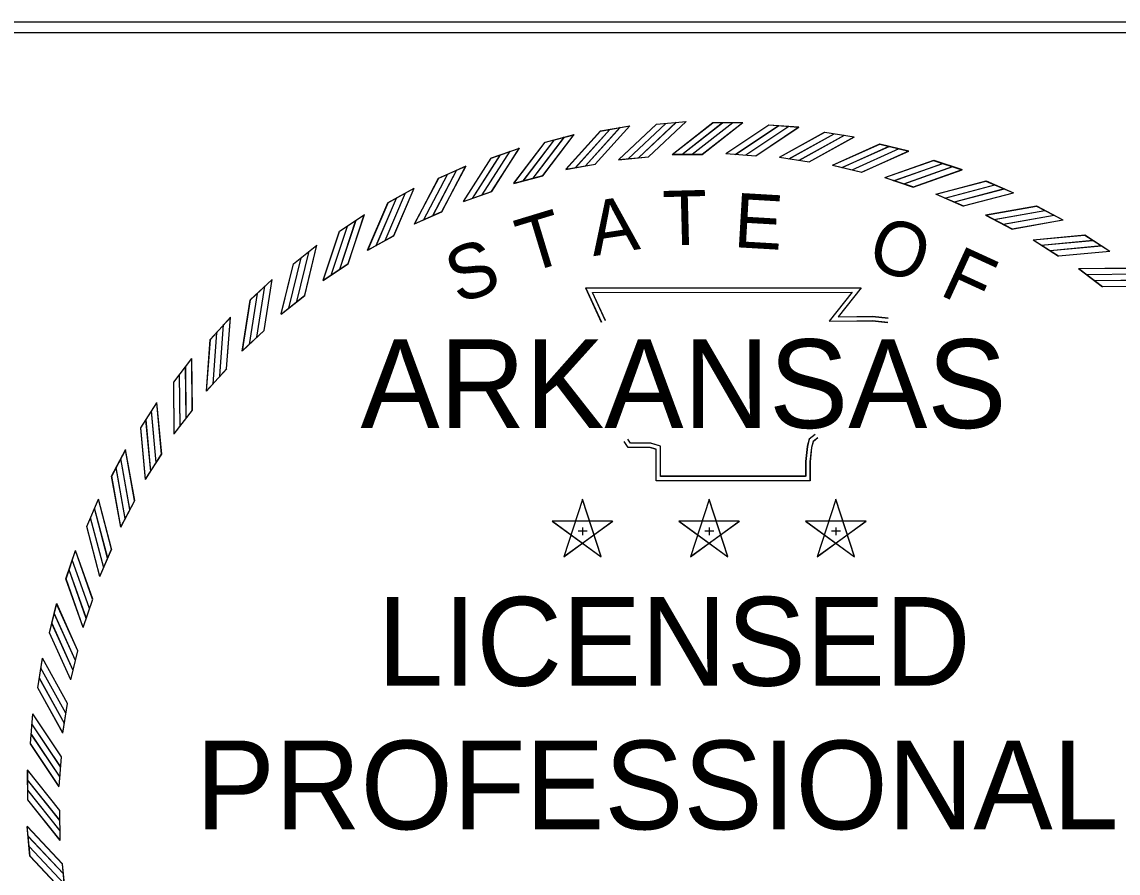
# Model space of a CAD drawing. Extents: x 0 to 1228740, y 0 to 152440.
# Drawn here: x 30.834 to 32.765, y 18.662 to 20.162 of the extents above; entities that cross this region are included whole.
import ezdxf

# ---------------------------------------------------------------- set-up
doc = ezdxf.new("R2010")
doc.units = 0
for name, color, linetype in [('R_Border', 7, 'Continuous'), ('R_No Plot', 7, 'Continuous'), ('R_Sheet Text', 7, 'Continuous'), ('STAMP', 7, 'Continuous')]:
    doc.layers.add(name, color=color, linetype=linetype)

msp = doc.modelspace()

# ---------------------------------------------------------------- linework, layer by layer
at = {"layer": 'R_Border'}
msp.add_line((29.1131, 20.1432), (33.4231, 20.1432), dxfattribs=at)
at = {"layer": 'R_No Plot'}
msp.add_lwpolyline([(30.6665, 20.1618), (33.4231, 20.1618), (33.4231, 17.4052), (30.6665, 17.4052)], close=True, dxfattribs=at)
at = {"layer": 'R_Sheet Text'}
for p, q in [((31.8532, 19.9696), (31.905, 19.9787)), ((31.9517, 19.9814), (32.0041, 19.9862)), ((32.0514, 19.9843), (32.104, 19.9843)), ((32.1499, 19.9804), (32.2025, 19.9765)), ((32.1499, 19.9803), (32.2024, 19.9765)), ((32.2483, 19.9676), (32.3003, 19.9594)), ((31.756, 19.9497), (31.8069, 19.9631)), ((31.6608, 19.9219), (31.7104, 19.9395)), ((32.0741, 19.9298), (32.1268, 19.9259)), ((32.0742, 19.9298), (32.1268, 19.9259)), ((32.3453, 19.9467), (32.3964, 19.9343)), ((31.7922, 19.902), (31.8442, 19.9111)), ((31.8853, 19.919), (31.9379, 19.9238)), ((31.9795, 19.9283), (32.0323, 19.9283)), ((32.1686, 19.9234), (32.2207, 19.9152)), ((32.4402, 19.9179), (32.4901, 19.9013)), ((31.5682, 19.8863), (31.6162, 19.9079)), ((31.7008, 19.8773), (31.7518, 19.8907)), ((32.2623, 19.9093), (32.3135, 19.8968)), ((32.3544, 19.8875), (32.4044, 19.8708)), ((32.5324, 19.8814), (32.5808, 19.8607)), ((31.4789, 19.8432), (31.5249, 19.8687)), ((31.6118, 19.8452), (31.6615, 19.8628)), ((32.4444, 19.8582), (32.4929, 19.8374)), ((32.6213, 19.8374), (32.6678, 19.8128)), ((31.3934, 19.7929), (31.4372, 19.8221)), ((31.5257, 19.8058), (31.5738, 19.8274)), ((32.5316, 19.8215), (32.5783, 19.7968)), ((31.4431, 19.7595), (31.4893, 19.785)), ((32.6156, 19.7777), (32.66, 19.7493)), ((32.7063, 19.7862), (32.7506, 19.7578)), ((31.3124, 19.7356), (31.3536, 19.7683)), ((31.3647, 19.7064), (31.4086, 19.7357)), ((32.6956, 19.7272), (32.7376, 19.6952)), ((31.2364, 19.6719), (31.2748, 19.7079)), ((31.2909, 19.6471), (31.3323, 19.6799)), ((31.1659, 19.6021), (31.2012, 19.6412)), ((31.2223, 19.582), (31.2608, 19.618)), ((31.1014, 19.5268), (31.1333, 19.5686)), ((31.1593, 19.5113), (31.1946, 19.5504)), ((31.0433, 19.4463), (31.0717, 19.4907)), ((31.1023, 19.4357), (31.1343, 19.4776)), ((30.9921, 19.3614), (31.0167, 19.4079)), ((31.0518, 19.3557), (31.0802, 19.4001)), ((30.9481, 19.2725), (30.9688, 19.3209)), ((31.008, 19.2717), (31.0327, 19.3183)), ((31.8214, 19.3203), (31.7885, 19.2193)), ((31.8542, 19.2194), (31.8215, 19.3205)), ((32.0446, 19.3203), (32.0117, 19.2193)), ((32.0774, 19.2194), (32.0447, 19.3205)), ((32.2678, 19.3203), (32.2349, 19.2193)), ((32.3006, 19.2194), (32.2679, 19.3205)), ((31.8745, 19.2818), (31.7682, 19.2819)), ((31.7683, 19.2818), (31.8542, 19.2193)), ((31.7886, 19.2194), (31.8746, 19.2818)), ((32.0977, 19.2818), (31.9914, 19.2819)), ((31.9915, 19.2818), (32.0774, 19.2193)), ((32.0118, 19.2194), (32.0978, 19.2818)), ((32.3209, 19.2818), (32.2147, 19.2819)), ((32.2147, 19.2818), (32.3006, 19.2193)), ((32.235, 19.2194), (32.321, 19.2818)), ((31.8138, 19.2648), (31.8296, 19.2648)), ((31.8215, 19.2705), (31.8215, 19.2572)), ((32.037, 19.2648), (32.0528, 19.2648)), ((32.0447, 19.2705), (32.0447, 19.2572)), ((32.2603, 19.2648), (32.276, 19.2648)), ((32.2679, 19.2705), (32.2679, 19.2572)), ((30.9116, 19.1803), (30.9282, 19.2302)), ((30.9713, 19.1844), (30.9921, 19.2329)), ((30.942, 19.0944), (30.9587, 19.1445)), ((30.8828, 19.0853), (30.8952, 19.1365)), ((30.9202, 19.0023), (30.9327, 19.0536)), ((30.8619, 18.9884), (30.8701, 19.0403)), ((30.9061, 18.9087), (30.9143, 18.9608)), ((30.8492, 18.89), (30.853, 18.9425)), ((30.8997, 18.8143), (30.9036, 18.8669)), ((30.8446, 18.7909), (30.8441, 18.8435)), ((30.9012, 18.7196), (30.9007, 18.7724)), ((30.8481, 18.6918), (30.8433, 18.7442)), ((30.9105, 18.6254), (30.9057, 18.6779))]:
    msp.add_line(p, q, dxfattribs=at)
for points in [[(31.7922, 19.9019), (31.8531, 19.9695)], [(31.8089, 19.9047), (31.8699, 19.9723)], [(31.8268, 19.9083), (31.8878, 19.9759)], [(31.8441, 19.9112), (31.9051, 19.9788)], [(31.8853, 19.919), (31.9516, 19.9813)], [(31.9022, 19.9203), (31.9685, 19.9827)], [(31.9203, 19.9224), (31.9867, 19.9848)], [(31.9378, 19.9239), (32.0042, 19.9862)], [(31.9795, 19.9282), (32.0513, 19.9842)], [(31.9964, 19.9281), (32.0682, 19.9841)], [(32.0147, 19.9285), (32.0865, 19.9845)], [(32.0322, 19.9283), (32.104, 19.9843)], [(32.0741, 19.9297), (32.1499, 19.9804)], [(32.0741, 19.9297), (32.1498, 19.9803)], [(32.091, 19.9283), (32.1668, 19.979)], [(32.091, 19.9283), (32.1667, 19.9789)], [(32.1092, 19.9274), (32.1851, 19.978)], [(32.1093, 19.9274), (32.185, 19.978)], [(32.1267, 19.9259), (32.2025, 19.9766)], [(32.1267, 19.9259), (32.2025, 19.9765)], [(32.1686, 19.9234), (32.2482, 19.9675)], [(31.7008, 19.8772), (31.756, 19.9497)], [(31.7172, 19.8814), (31.7724, 19.9538)], [(31.7348, 19.8864), (31.79, 19.9589)], [(31.7518, 19.8907), (31.807, 19.9632)], [(32.1853, 19.9206), (32.2649, 19.9647)], [(32.2034, 19.9182), (32.283, 19.9623)], [(32.2207, 19.9153), (32.3003, 19.9594)], [(31.6449, 19.8571), (31.6939, 19.9338)], [(31.6614, 19.8628), (31.7105, 19.9395)], [(32.2622, 19.9093), (32.3452, 19.9467)], [(32.2786, 19.9051), (32.3616, 19.9425)], [(32.2965, 19.9012), (32.3795, 19.9386)], [(32.3134, 19.8969), (32.3965, 19.9343)], [(31.6117, 19.8451), (31.6608, 19.9218)], [(31.6278, 19.8506), (31.6768, 19.9273)], [(32.3543, 19.8875), (32.4401, 19.9179)], [(32.3703, 19.882), (32.4561, 19.9124)], [(31.5412, 19.8125), (31.5837, 19.893)], [(31.5577, 19.8204), (31.6002, 19.9009)], [(31.5737, 19.8274), (31.6162, 19.908)], [(32.3878, 19.8766), (32.4736, 19.907)], [(32.4044, 19.8709), (32.4902, 19.9013)], [(31.5257, 19.8057), (31.5682, 19.8862)], [(32.4443, 19.8581), (32.5323, 19.8814)], [(32.4598, 19.8513), (32.5478, 19.8746)], [(31.4738, 19.7766), (31.5095, 19.8604)], [(31.4892, 19.785), (31.525, 19.8687)], [(32.4768, 19.8445), (32.5648, 19.8678)], [(32.4928, 19.8375), (32.5809, 19.8607)], [(31.4431, 19.7594), (31.4788, 19.8431)], [(31.458, 19.7674), (31.4937, 19.8512)], [(32.5316, 19.8215), (32.6212, 19.8374)], [(31.4085, 19.7357), (31.4372, 19.8221)], [(32.5465, 19.8134), (32.6361, 19.8293)], [(32.5628, 19.8052), (32.6525, 19.8211)], [(31.3789, 19.7156), (31.4076, 19.8021)], [(31.3939, 19.7261), (31.4225, 19.8125)], [(32.5782, 19.7969), (32.6679, 19.8128)], [(31.3647, 19.7064), (31.3934, 19.7928)], [(32.6155, 19.7777), (32.7062, 19.7862)], [(32.6297, 19.7685), (32.7204, 19.7769)], [(31.3183, 19.6691), (31.3398, 19.7576)], [(31.3322, 19.6799), (31.3536, 19.7684)], [(32.6453, 19.7589), (32.736, 19.7674)], [(32.66, 19.7494), (32.7506, 19.7578)], [(31.3043, 19.6575), (31.3257, 19.746)], [(31.2909, 19.6471), (31.3124, 19.7356)], [(32.6956, 19.7272), (32.7866, 19.7281)], [(32.7089, 19.7168), (32.8, 19.7177)], [(31.2607, 19.618), (31.2748, 19.708)], [(32.7237, 19.706), (32.8147, 19.707)], [(31.2347, 19.5933), (31.2488, 19.6833)], [(31.2478, 19.6061), (31.2619, 19.6961)], [(31.8553, 19.6321), (31.8272, 19.6928), (32.3126, 19.6931), (32.272, 19.6422), (32.305, 19.6426), (32.3325, 19.643), (32.36, 19.64)], [(31.8623, 19.6353), (31.8393, 19.6852), (32.2966, 19.6854), (32.2559, 19.6343), (32.3051, 19.6349), (32.3322, 19.6353), (32.3592, 19.6323)], [(32.7375, 19.6953), (32.8286, 19.6962)], [(31.2223, 19.5819), (31.2363, 19.6718)], [(31.1946, 19.5504), (31.2012, 19.6412)], [(31.1827, 19.5375), (31.1893, 19.6283)], [(31.1593, 19.5112), (31.1659, 19.6021)], [(31.1707, 19.5237), (31.1773, 19.6145)], [(31.1342, 19.4776), (31.1333, 19.5687)], [(31.1235, 19.4638), (31.1225, 19.5548)], [(31.1023, 19.4356), (31.1014, 19.5267)], [(31.1127, 19.449), (31.1118, 19.54)], [(31.0801, 19.4001), (31.0717, 19.4907)], [(31.0706, 19.3854), (31.0621, 19.476)], [(31.0518, 19.3556), (31.0433, 19.4462)], [(31.061, 19.3698), (31.0526, 19.4604)], [(32.2361, 19.4287), (32.2278, 19.422), (32.2251, 19.4119), (32.2223, 19.3868), (32.2223, 19.3532), (31.9514, 19.3532), (31.9514, 19.3985), (31.9514, 19.4086), (31.9404, 19.4119), (31.9019, 19.4119), (31.895, 19.4224)], [(32.2312, 19.4347), (32.2211, 19.4264), (32.2175, 19.4134), (32.2146, 19.3872), (32.2146, 19.3609), (31.9591, 19.3609), (31.9591, 19.3985), (31.9591, 19.4142), (31.9416, 19.4196), (31.906, 19.4196), (31.9015, 19.4266)], [(31.0326, 19.3183), (31.0167, 19.408)], [(31.0243, 19.3029), (31.0084, 19.3925)], [(31.0161, 19.2865), (31.0002, 19.3762)], [(31.008, 19.2716), (30.9921, 19.3613)], [(30.992, 19.2329), (30.9688, 19.3209)], [(30.985, 19.2168), (30.9617, 19.3049)], [(30.9714, 19.1844), (30.9481, 19.2724)], [(30.9782, 19.1999), (30.9549, 19.2879)], [(30.9586, 19.1444), (30.9282, 19.2303)], [(30.9475, 19.1104), (30.9171, 19.1962)], [(30.9529, 19.1279), (30.9225, 19.2137)], [(30.942, 19.0944), (30.9116, 19.1802)], [(30.9283, 19.0365), (30.8909, 19.1195)], [(30.9326, 19.0535), (30.8952, 19.1365)], [(30.9244, 19.0187), (30.887, 19.1017)], [(30.9202, 19.0023), (30.8828, 19.0853)], [(30.9113, 18.9435), (30.8672, 19.0231)], [(30.9142, 18.9608), (30.8701, 19.0404)], [(30.9089, 18.9254), (30.8648, 19.005)], [(30.9061, 18.9087), (30.862, 18.9883)], [(30.9021, 18.8493), (30.8515, 18.9251)], [(30.9036, 18.8668), (30.853, 18.9425)], [(30.9012, 18.8311), (30.8506, 18.9068)], [(30.8998, 18.8142), (30.8492, 18.8899)], [(30.9007, 18.7723), (30.844, 18.8436)], [(30.9007, 18.7548), (30.844, 18.826)], [(30.9013, 18.7365), (30.8446, 18.8078)], [(30.9013, 18.7196), (30.8446, 18.7908)], [(30.9056, 18.6779), (30.8433, 18.7442)], [(30.9071, 18.6604), (30.8447, 18.7268)], [(30.9091, 18.6422), (30.8468, 18.7086)], [(30.9105, 18.6254), (30.8482, 18.6917)]]:
    msp.add_lwpolyline(points, dxfattribs=at)
at = {"layer": 'STAMP'}
for p, q in [((31.8534, 19.9698), (31.9052, 19.9789)), ((31.9519, 19.9816), (32.0043, 19.9864)), ((32.0515, 19.9845), (32.1041, 19.9845)), ((32.1501, 19.9806), (32.2027, 19.9767)), ((32.1501, 19.9805), (32.2026, 19.9767)), ((32.2485, 19.9678), (32.3004, 19.9596)), ((31.7562, 19.9499), (31.8071, 19.9633)), ((31.661, 19.9221), (31.7106, 19.9396)), ((32.0743, 19.93), (32.127, 19.9261)), ((32.0744, 19.93), (32.127, 19.9261)), ((32.3454, 19.9469), (32.3966, 19.9345)), ((31.7924, 19.9022), (31.8443, 19.9113)), ((31.8855, 19.9192), (31.938, 19.924)), ((31.9797, 19.9285), (32.0324, 19.9285)), ((32.1688, 19.9236), (32.2209, 19.9154)), ((32.2624, 19.9095), (32.3137, 19.897)), ((32.4404, 19.9181), (32.4903, 19.9015)), ((31.5684, 19.8865), (31.6164, 19.9081)), ((31.701, 19.8775), (31.752, 19.8909)), ((32.3545, 19.8877), (32.4046, 19.871)), ((32.5326, 19.8816), (32.581, 19.8609)), ((31.479, 19.8434), (31.5251, 19.8689)), ((31.6119, 19.8454), (31.6616, 19.863)), ((32.4445, 19.8583), (32.493, 19.8376)), ((32.6215, 19.8376), (32.668, 19.813)), ((31.3935, 19.7931), (31.4373, 19.8222)), ((31.5258, 19.806), (31.5739, 19.8276)), ((32.5318, 19.8217), (32.5784, 19.797)), ((31.4433, 19.7596), (31.4894, 19.7852)), ((32.6158, 19.7779), (32.6602, 19.7495)), ((32.7064, 19.7864), (32.7508, 19.758)), ((31.3125, 19.7358), (31.3537, 19.7685)), ((31.3648, 19.7066), (31.4087, 19.7359)), ((32.6958, 19.7274), (32.7377, 19.6954)), ((31.2365, 19.6721), (31.2749, 19.7081)), ((31.2911, 19.6473), (31.3324, 19.6801)), ((31.166, 19.6023), (31.2013, 19.6414)), ((31.2224, 19.5821), (31.2609, 19.6182)), ((31.1015, 19.527), (31.1334, 19.5688)), ((31.1594, 19.5115), (31.1948, 19.5506)), ((31.0434, 19.4465), (31.0718, 19.4908)), ((31.1024, 19.4359), (31.1344, 19.4778)), ((30.9922, 19.3616), (31.0169, 19.4081)), ((31.0519, 19.3558), (31.0803, 19.4003)), ((30.9482, 19.2727), (30.9689, 19.321)), ((31.0081, 19.2719), (31.0328, 19.3185)), ((31.8215, 19.3205), (31.7886, 19.2195)), ((31.8543, 19.2196), (31.8216, 19.3206)), ((32.0448, 19.3205), (32.0118, 19.2195)), ((32.0776, 19.2196), (32.0448, 19.3206)), ((32.268, 19.3205), (32.2351, 19.2195)), ((32.3008, 19.2196), (32.2681, 19.3206)), ((31.8746, 19.282), (31.7684, 19.2821)), ((31.7685, 19.282), (31.8544, 19.2194)), ((31.7887, 19.2196), (31.8748, 19.2819)), ((32.0978, 19.282), (31.9916, 19.2821)), ((31.9917, 19.282), (32.0776, 19.2194)), ((32.012, 19.2196), (32.098, 19.2819)), ((32.3211, 19.282), (32.2148, 19.2821)), ((32.2149, 19.282), (32.3008, 19.2194)), ((32.2352, 19.2196), (32.3212, 19.2819)), ((31.814, 19.265), (31.8298, 19.265)), ((31.8216, 19.2707), (31.8216, 19.2573)), ((32.0372, 19.265), (32.053, 19.265)), ((32.0449, 19.2707), (32.0449, 19.2573)), ((32.2604, 19.265), (32.2762, 19.265)), ((32.2681, 19.2707), (32.2681, 19.2573)), ((30.9117, 19.1804), (30.9283, 19.2304)), ((30.9715, 19.1846), (30.9922, 19.2331)), ((30.9421, 19.0946), (30.9588, 19.1447)), ((30.8829, 19.0855), (30.8953, 19.1366)), ((30.862, 18.9885), (30.8702, 19.0405)), ((30.9203, 19.0025), (30.9328, 19.0537)), ((30.9062, 18.9089), (30.9144, 18.961)), ((30.8493, 18.8902), (30.8531, 18.9426)), ((30.8998, 18.8144), (30.9037, 18.867)), ((30.8447, 18.7911), (30.8442, 18.8437)), ((30.9013, 18.7198), (30.9008, 18.7725)), ((30.8483, 18.6919), (30.8434, 18.7443)), ((30.9106, 18.6256), (30.9058, 18.6781))]:
    msp.add_line(p, q, dxfattribs=at)
for points in [[(31.7923, 19.9021), (31.8533, 19.9697)], [(31.809, 19.9049), (31.87, 19.9725)], [(31.8269, 19.9085), (31.8879, 19.9761)], [(31.8442, 19.9114), (31.9052, 19.979)], [(31.8854, 19.9191), (31.9518, 19.9815)], [(31.9023, 19.9205), (31.9687, 19.9829)], [(31.9205, 19.9226), (31.9868, 19.985)], [(31.9379, 19.9241), (32.0043, 19.9864)], [(31.9796, 19.9284), (32.0514, 19.9844)], [(31.9966, 19.9283), (32.0684, 19.9843)], [(32.0149, 19.9287), (32.0867, 19.9847)], [(32.0324, 19.9285), (32.1042, 19.9845)], [(32.0742, 19.9299), (32.15, 19.9806)], [(32.0743, 19.9299), (32.15, 19.9805)], [(32.0911, 19.9285), (32.1669, 19.9792)], [(32.0912, 19.9285), (32.1669, 19.9791)], [(32.1094, 19.9276), (32.1852, 19.9782)], [(32.1094, 19.9276), (32.1851, 19.9782)], [(32.1269, 19.9261), (32.2027, 19.9768)], [(32.1269, 19.9261), (32.2026, 19.9767)], [(32.1687, 19.9236), (32.2484, 19.9677)], [(31.7009, 19.8774), (31.7561, 19.9499)], [(31.7173, 19.8816), (31.7725, 19.954)], [(31.7349, 19.8866), (31.7901, 19.9591)], [(31.7519, 19.8909), (31.8071, 19.9634)], [(32.1854, 19.9208), (32.2651, 19.9649)], [(32.2036, 19.9183), (32.2832, 19.9625)], [(32.2209, 19.9155), (32.3005, 19.9596)], [(31.645, 19.8573), (31.694, 19.934)], [(31.6616, 19.863), (31.7106, 19.9397)], [(32.2623, 19.9095), (32.3454, 19.9469)], [(32.2788, 19.9053), (32.3618, 19.9427)], [(32.2966, 19.9014), (32.3796, 19.9388)], [(32.3136, 19.8971), (32.3966, 19.9345)], [(31.6119, 19.8453), (31.6609, 19.922)], [(31.6279, 19.8508), (31.6769, 19.9275)], [(32.3545, 19.8877), (32.4403, 19.9181)], [(32.3705, 19.8822), (32.4563, 19.9126)], [(31.5413, 19.8127), (31.5838, 19.8932)], [(31.5578, 19.8206), (31.6003, 19.9011)], [(31.5739, 19.8276), (31.6164, 19.9082)], [(32.388, 19.8768), (32.4738, 19.9072)], [(32.4045, 19.8711), (32.4904, 19.9015)], [(31.5258, 19.8059), (31.5683, 19.8864)], [(32.4445, 19.8583), (32.5325, 19.8816)], [(32.46, 19.8515), (32.548, 19.8748)], [(31.4739, 19.7768), (31.5097, 19.8606)], [(31.4894, 19.7852), (31.5251, 19.8689)], [(32.4769, 19.8447), (32.565, 19.868)], [(32.493, 19.8377), (32.581, 19.8609)], [(31.4433, 19.7596), (31.479, 19.8433)], [(31.4581, 19.7676), (31.4939, 19.8514)], [(32.5317, 19.8217), (32.6214, 19.8376)], [(31.4087, 19.7359), (31.4374, 19.8223)], [(32.5466, 19.8136), (32.6363, 19.8295)], [(32.563, 19.8054), (32.6526, 19.8213)], [(32.5784, 19.7971), (32.6681, 19.813)], [(31.379, 19.7158), (31.4077, 19.8022)], [(31.394, 19.7263), (31.4227, 19.8127)], [(31.3648, 19.7066), (31.3935, 19.793)], [(32.6157, 19.7779), (32.7064, 19.7864)], [(32.6299, 19.7687), (32.7205, 19.7771)], [(31.3185, 19.6693), (31.3399, 19.7578)], [(31.3323, 19.6801), (31.3538, 19.7686)], [(32.6455, 19.7591), (32.7361, 19.7676)], [(32.6602, 19.7495), (32.7508, 19.758)], [(31.291, 19.6473), (31.3125, 19.7357)], [(31.3044, 19.6577), (31.3259, 19.7461)], [(32.6957, 19.7274), (32.7868, 19.7283)], [(32.7091, 19.717), (32.8002, 19.7179)], [(31.2608, 19.6182), (31.2749, 19.7082)], [(32.7239, 19.7062), (32.8149, 19.7071)], [(31.2349, 19.5935), (31.2489, 19.6835)], [(31.2479, 19.6063), (31.262, 19.6963)], [(31.8554, 19.6323), (31.8274, 19.693), (32.3127, 19.6933), (32.2722, 19.6424), (32.3052, 19.6428), (32.3327, 19.6431), (32.3602, 19.6401)], [(31.8624, 19.6355), (31.8394, 19.6853), (32.2968, 19.6856), (32.2561, 19.6345), (32.3053, 19.6351), (32.3323, 19.6355), (32.3594, 19.6325)], [(32.7377, 19.6954), (32.8288, 19.6964)], [(31.2224, 19.5821), (31.2365, 19.672)], [(31.1947, 19.5506), (31.2013, 19.6414)], [(31.1828, 19.5377), (31.1894, 19.6285)], [(31.1594, 19.5114), (31.166, 19.6022)], [(31.1709, 19.5239), (31.1775, 19.6147)], [(31.1344, 19.4778), (31.1334, 19.5688)], [(31.1236, 19.464), (31.1227, 19.555)], [(31.1024, 19.4358), (31.1015, 19.5269)], [(31.1128, 19.4492), (31.1119, 19.5402)], [(31.0803, 19.4002), (31.0718, 19.4909)], [(31.0707, 19.3856), (31.0622, 19.4762)], [(31.0519, 19.3558), (31.0434, 19.4464)], [(31.0612, 19.3699), (31.0527, 19.4606)], [(32.2363, 19.4289), (32.228, 19.4222), (32.2252, 19.4121), (32.2225, 19.3869), (32.2225, 19.3534), (31.9516, 19.3534), (31.9516, 19.3987), (31.9516, 19.4087), (31.9406, 19.4121), (31.902, 19.4121), (31.8952, 19.4225)], [(32.2314, 19.4349), (32.2212, 19.4266), (32.2177, 19.4135), (32.2148, 19.3873), (32.2148, 19.3611), (31.9592, 19.3611), (31.9592, 19.3987), (31.9592, 19.4144), (31.9417, 19.4198), (31.9062, 19.4198), (31.9016, 19.4267)], [(31.0327, 19.3185), (31.0168, 19.4081)], [(31.0244, 19.3031), (31.0085, 19.3927)], [(31.0162, 19.2867), (31.0003, 19.3764)], [(31.0081, 19.2718), (30.9922, 19.3615)], [(30.9921, 19.2331), (30.9689, 19.3211)], [(30.9851, 19.217), (30.9618, 19.3051)], [(30.9715, 19.1845), (30.9482, 19.2726)], [(30.9783, 19.2), (30.955, 19.2881)], [(30.9587, 19.1446), (30.9283, 19.2304)], [(30.9476, 19.1106), (30.9172, 19.1964)], [(30.953, 19.128), (30.9226, 19.2138)], [(30.9421, 19.0945), (30.9117, 19.1803)], [(30.9284, 19.0367), (30.891, 19.1197)], [(30.9327, 19.0537), (30.8953, 19.1367)], [(30.9245, 19.0188), (30.8871, 19.1018)], [(30.9203, 19.0024), (30.8829, 19.0854)], [(30.9143, 18.9609), (30.8702, 19.0406)], [(30.9115, 18.9436), (30.8673, 19.0233)], [(30.909, 18.9255), (30.8649, 19.0052)], [(30.9062, 18.9088), (30.8621, 18.9884)], [(30.9022, 18.8495), (30.8516, 18.9252)], [(30.9037, 18.867), (30.8531, 18.9427)], [(30.9013, 18.8312), (30.8507, 18.907)], [(30.8999, 18.8144), (30.8493, 18.8901)], [(30.9008, 18.7724), (30.8441, 18.8437)], [(30.9008, 18.7549), (30.8441, 18.8262)], [(30.9014, 18.7366), (30.8447, 18.8079)], [(30.9014, 18.7197), (30.8447, 18.791)], [(30.9057, 18.678), (30.8434, 18.7444)], [(30.9072, 18.6605), (30.8448, 18.7269)], [(30.9093, 18.6424), (30.8469, 18.7087)], [(30.9107, 18.6255), (30.8483, 18.6919)]]:
    msp.add_lwpolyline(points, dxfattribs=at)

# ---------------------------------------------------------------- texts
at = {"layer": 'R_Sheet Text'}
for s, height, rotation, p in [('T', 0.0959, 1.4789, (31.9639, 19.7678)), ('T', 0.0957, 1.4789, (31.9641, 19.768)), ('E', 0.0957, 356.672, (32.0866, 19.7651)), ('A', 0.0957, 8.6788, (31.8405, 19.7489)), ('T', 0.0957, 16.9015, (31.7243, 19.7186)), ('O', 0.0957, 341.2218, (32.3191, 19.7322)), ('S', 0.0957, 19.7726, (31.6025, 19.6639)), ('F', 0.0957, 335.3628, (32.4481, 19.6818))]:
    msp.add_text(s, height=height, rotation=rotation, dxfattribs=at).set_placement(p)
for s, height, p in [('ARKANSAS', 0.15625, (31.4305, 19.4462)), ('LICENSED', 0.15625, (31.4603, 18.992)), ('PROFESSIONAL', 0.156246, (31.1403, 18.7391))]:
    msp.add_text(s, height=height, dxfattribs=at).set_placement(p)
at = {"layer": 'STAMP'}
for s, height, rotation, p in [('T', 0.0959, 1.4789, (31.9641, 19.768)), ('T', 0.0957, 1.4789, (31.9643, 19.7682)), ('E', 0.0957, 356.672, (32.0868, 19.7653)), ('T', 0.0957, 16.9015, (31.7244, 19.7188)), ('A', 0.0957, 8.6788, (31.8406, 19.7491)), ('O', 0.0957, 341.2218, (32.3193, 19.7324)), ('S', 0.0957, 19.7726, (31.6027, 19.6641)), ('F', 0.0957, 335.3628, (32.4483, 19.682))]:
    msp.add_text(s, height=height, rotation=rotation, dxfattribs=at).set_placement(p)
for s, height, p in [('ARKANSAS', 0.15625, (31.4306, 19.4463)), ('LICENSED', 0.15625, (31.4604, 18.9922)), ('PROFESSIONAL', 0.156252, (31.1405, 18.7392))]:
    msp.add_text(s, height=height, dxfattribs=at).set_placement(p)

doc.saveas('drawing.dxf')
